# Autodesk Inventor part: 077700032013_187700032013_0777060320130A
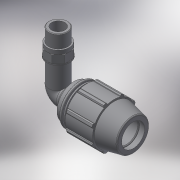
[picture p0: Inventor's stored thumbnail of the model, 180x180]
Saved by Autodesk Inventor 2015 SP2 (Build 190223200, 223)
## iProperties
Created: 2017-02
Part Number: 077700032013_187700032013_0777060320130A
Material: Generic
Description: PLASSON 90° ELBOW MALE WITH INTEGRAL BRASS THREAD 32-1.1/4"
Document SubType Name: Modeling
Designer: KIM
Mass: 174.249 g
Surface Area: 431.906 cm^2
Volume: 174.249 cm^3
Density: 1 g/cm^3
Appearance: Default
Author: KIM
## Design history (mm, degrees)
derived "07770.ipt"
feature "Solid1::07770.ipt"
tag "TaggingFeature1"
body "Solid1"
other parameters: "d2" = 32, "d4" = 8.66667, "d5" = 26, "d7" = 64, "d9" = 14.85714, "d11" = 3.46667, "d13" = 120 deg, "d14" = 44.8, "d15" = 12 deg, "d16" = 55.68, "d18" = 1.6, "d19" = 35 deg, "d20" = 17.5 deg, "d21" = 59.52, "d23" = 0, "d25" = 360 deg, "d27" = 1.28, "d33" = 0.64, "d42" = 38.48, "d43" = 1.92, "d46" = 0.96, "d51" = 104, "d68" = 6.93333, "d72" = 82, "d73" = 41.91, "d74" = 22, "d75" = 48.1965, "d76" = 29.337, "d79" = 16.764, "d80" = 1.2573, "d83" = 0, "d84" = 0, "d91" = 48, "d93" = 67, "d94" = 41.91, "d95" = 29.337, "d96" = 6.93333, "d97" = 50 deg, "d98" = 1.73333, "d99" = 54.0096, "d100" = 1.73333, "d101" = 1.73333, "d105" = 2.2, "d106" = 50.292, "d107" = 22, "d108" = 13.2, "d109" = 0, "d_" = 32, "E_" = 64, "A_" = 104, "l_" = 67, "l_2" = 22, "A_1" = 82, "R_" = 41.91
